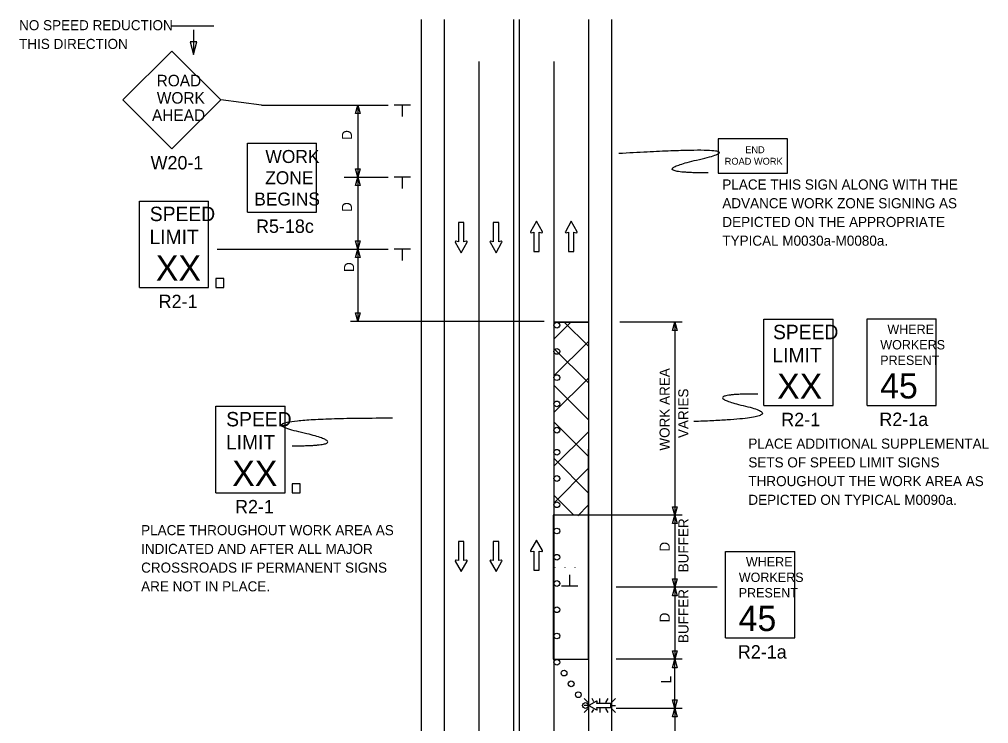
# Model space of a CAD drawing. Extents: x 16747 to 18480, y 5932 to 6921.
# Drawn here: x 16747 to 17419, y 6432 to 6921 of the extents above; entities that cross this region are included whole.
import ezdxf

# ---------------------------------------------------------------- set-up
doc = ezdxf.new("R2010")
doc.units = 0
for name, color, linetype in [('ALI_LEGAL_EX', 7, 'Continuous'), ('MT_SCRATCH_LEVEL_E', 7, 'Continuous'), ('PAVT_EDGE_EX', 7, 'Continuous'), ('TRAFFIC_SIGNS_PR', 7, 'Continuous'), ('TYPICAL_TEXT_DIMEN_PR', 7, 'Continuous')]:
    doc.layers.add(name, color=color, linetype=linetype)

msp = doc.modelspace()

# ---------------------------------------------------------------- linework, layer by layer
at = {"layer": 'ALI_LEGAL_EX'}
for p, q in [((17065.33, 6891.74), (17065.33, 6062.55)), ((17117.33, 6891.74), (17117.33, 6062.55))]:
    msp.add_line(p, q, dxfattribs=at)
for points in [[(17065.33, 6809.08), (17065.33, 6784.08)], [(17117.33, 6809.08), (17117.33, 6784.08)], [(17065.33, 6709.08), (17065.33, 6684.08)], [(17117.33, 6709.08), (17117.33, 6684.08)], [(17065.33, 6609.08), (17065.33, 6584.08)], [(17117.33, 6609.08), (17117.33, 6584.08)], [(17117.33, 6541.14), (17117.33, 6516.14)], [(17065.33, 6509.08), (17065.33, 6484.08)]]:
    msp.add_lwpolyline(points, dxfattribs=at)
at = {"layer": 'MT_SCRATCH_LEVEL_E'}
for p, q in [((17055, 6779.96), (17051.26, 6779.96)), ((17051.26, 6779.96), (17051.26, 6766.71)), ((17055, 6779.96), (17051.26, 6779.96)), ((17051.26, 6779.96), (17051.26, 6766.71)), ((17055, 6766.71), (17055, 6779.96)), ((17055, 6766.71), (17055, 6779.96)), ((17079.07, 6779.96), (17075.33, 6779.96)), ((17075.33, 6779.96), (17075.33, 6766.71)), ((17079.07, 6779.96), (17075.33, 6779.96)), ((17075.33, 6779.96), (17075.33, 6766.71)), ((17079.07, 6766.71), (17079.07, 6779.96)), ((17079.07, 6766.71), (17079.07, 6779.96)), ((17105.26, 6780.91), (17101.15, 6773.67)), ((17105.26, 6780.91), (17101.15, 6773.67)), ((17109.41, 6773.67), (17105.26, 6780.91)), ((17109.41, 6773.67), (17105.26, 6780.91)), ((17129.43, 6780.91), (17125.32, 6773.67)), ((17129.43, 6780.91), (17125.32, 6773.67)), ((17133.58, 6773.67), (17129.43, 6780.91)), ((17133.58, 6773.67), (17129.43, 6780.91)), ((17101.63, 6772.99), (17103.41, 6773.3)), ((17101.63, 6772.99), (17103.41, 6773.3)), ((17103.41, 6773.3), (17103.41, 6760.04)), ((17103.41, 6773.3), (17103.41, 6760.04)), ((17107.15, 6760.04), (17107.15, 6773.3)), ((17107.15, 6773.3), (17108.93, 6772.99)), ((17107.15, 6760.04), (17107.15, 6773.3)), ((17107.15, 6773.3), (17108.93, 6772.99)), ((17125.8, 6772.99), (17127.58, 6773.3)), ((17125.8, 6772.99), (17127.58, 6773.3)), ((17127.58, 6773.3), (17127.58, 6760.04)), ((17127.58, 6773.3), (17127.58, 6760.04)), ((17131.32, 6760.04), (17131.32, 6773.3)), ((17131.32, 6773.3), (17133.1, 6772.99)), ((17131.32, 6760.04), (17131.32, 6773.3)), ((17131.32, 6773.3), (17133.1, 6772.99)), ((17049, 6766.34), (17053.15, 6759.1)), ((17049, 6766.34), (17053.15, 6759.1)), ((17051.26, 6766.71), (17049.48, 6767.02)), ((17051.26, 6766.71), (17049.48, 6767.02)), ((17053.15, 6759.1), (17057.26, 6766.34)), ((17053.15, 6759.1), (17057.26, 6766.34)), ((17056.78, 6767.02), (17055, 6766.71)), ((17056.78, 6767.02), (17055, 6766.71)), ((17073.07, 6766.34), (17077.22, 6759.1)), ((17073.07, 6766.34), (17077.22, 6759.1)), ((17075.33, 6766.71), (17073.55, 6767.02)), ((17075.33, 6766.71), (17073.55, 6767.02)), ((17077.22, 6759.1), (17081.33, 6766.34)), ((17077.22, 6759.1), (17081.33, 6766.34)), ((17080.85, 6767.02), (17079.07, 6766.71)), ((17080.85, 6767.02), (17079.07, 6766.71)), ((17103.41, 6760.04), (17107.15, 6760.04)), ((17103.41, 6760.04), (17107.15, 6760.04)), ((17127.58, 6760.04), (17131.32, 6760.04)), ((17127.58, 6760.04), (17131.32, 6760.04)), ((17055, 6558.64), (17051.26, 6558.64)), ((17051.26, 6558.64), (17051.26, 6545.38)), ((17055, 6558.64), (17051.26, 6558.64)), ((17051.26, 6558.64), (17051.26, 6545.38)), ((17055, 6545.38), (17055, 6558.64)), ((17055, 6545.38), (17055, 6558.64)), ((17079.07, 6558.64), (17075.33, 6558.64)), ((17075.33, 6558.64), (17075.33, 6545.38)), ((17079.07, 6558.64), (17075.33, 6558.64)), ((17075.33, 6558.64), (17075.33, 6545.38)), ((17079.07, 6545.38), (17079.07, 6558.64)), ((17079.07, 6545.38), (17079.07, 6558.64)), ((17105.26, 6559.59), (17101.15, 6552.35)), ((17105.26, 6559.59), (17101.15, 6552.35)), ((17109.41, 6552.35), (17105.26, 6559.59)), ((17109.41, 6552.35), (17105.26, 6559.59)), ((17101.63, 6551.66), (17103.41, 6551.98)), ((17101.63, 6551.66), (17103.41, 6551.98)), ((17103.41, 6551.98), (17103.41, 6538.72)), ((17103.41, 6551.98), (17103.41, 6538.72)), ((17107.15, 6538.72), (17107.15, 6551.98)), ((17107.15, 6551.98), (17108.93, 6551.66)), ((17107.15, 6538.72), (17107.15, 6551.98)), ((17107.15, 6551.98), (17108.93, 6551.66)), ((17049, 6545.01), (17053.15, 6537.77)), ((17049, 6545.01), (17053.15, 6537.77)), ((17051.26, 6545.38), (17049.48, 6545.7)), ((17051.26, 6545.38), (17049.48, 6545.7)), ((17053.15, 6537.77), (17057.26, 6545.01)), ((17053.15, 6537.77), (17057.26, 6545.01)), ((17056.78, 6545.7), (17055, 6545.38)), ((17056.78, 6545.7), (17055, 6545.38)), ((17073.07, 6545.01), (17077.22, 6537.77)), ((17073.07, 6545.01), (17077.22, 6537.77)), ((17075.33, 6545.38), (17073.55, 6545.7)), ((17075.33, 6545.38), (17073.55, 6545.7)), ((17077.22, 6537.77), (17081.33, 6545.01)), ((17077.22, 6537.77), (17081.33, 6545.01)), ((17080.85, 6545.7), (17079.07, 6545.38)), ((17080.85, 6545.7), (17079.07, 6545.38)), ((17103.41, 6538.72), (17107.15, 6538.72)), ((17103.41, 6538.72), (17107.15, 6538.72))]:
    msp.add_line(p, q, dxfattribs=at)
for centre, start, end in [((17101.56, 6773.45), 150.42484, 279.96381), ((17101.56, 6773.45), 150.42484, 279.96381), ((17109, 6773.45), 260.03619, 29.77312), ((17109, 6773.45), 260.03619, 29.77312), ((17125.73, 6773.45), 150.42484, 279.96381), ((17125.73, 6773.45), 150.42484, 279.96381), ((17133.17, 6773.45), 260.03619, 29.77312), ((17133.17, 6773.45), 260.03619, 29.77312), ((17049.41, 6766.56), 80.03619, 209.77312), ((17049.41, 6766.56), 80.03619, 209.77312), ((17056.85, 6766.56), 330.42484, 99.96381), ((17056.85, 6766.56), 330.42484, 99.96381), ((17073.48, 6766.56), 80.03619, 209.77312), ((17073.48, 6766.56), 80.03619, 209.77312), ((17080.92, 6766.56), 330.42484, 99.96381), ((17080.92, 6766.56), 330.42484, 99.96381), ((17101.56, 6552.12), 150.42484, 279.96381), ((17101.56, 6552.12), 150.42484, 279.96381), ((17109, 6552.12), 260.03619, 29.77312), ((17109, 6552.12), 260.03619, 29.77312), ((17049.41, 6545.24), 80.03619, 209.77312), ((17049.41, 6545.24), 80.03619, 209.77312), ((17056.85, 6545.24), 330.42484, 99.96381), ((17056.85, 6545.24), 330.42484, 99.96381), ((17073.48, 6545.24), 80.03619, 209.77312), ((17073.48, 6545.24), 80.03619, 209.77312), ((17080.92, 6545.24), 330.42484, 99.96381), ((17080.92, 6545.24), 330.42484, 99.96381)]:
    msp.add_arc(centre, 0.463, start, end, dxfattribs=at)
at = {"layer": 'PAVT_EDGE_EX'}
for p, q in [((17025.33, 6921.02), (17025.33, 6117.01)), ((17041.33, 6921.02), (17041.33, 6117.01)), ((17089.33, 6921.02), (17089.33, 6117.01)), ((17093.33, 6921.02), (17093.33, 6117.01)), ((17141.33, 6921.02), (17141.33, 6117.01)), ((17157.33, 6921.02), (17157.33, 6117.01)), ((17141.33, 6710.93), (17117.33, 6710.93)), ((17117.33, 6710.93), (17141.33, 6710.93)), ((17117.33, 6699.03), (17129.23, 6710.93)), ((17141.33, 6694.12), (17124.52, 6710.93)), ((17117.33, 6673.58), (17141.33, 6697.58)), ((17141.33, 6668.67), (17117.33, 6692.67)), ((17117.33, 6648.12), (17141.33, 6672.12)), ((17141.33, 6643.21), (17117.33, 6667.21)), ((17141.33, 6617.76), (17117.33, 6641.76)), ((17117.38, 6610.86), (17141.33, 6634.81)), ((17141.33, 6508.99), (17141.33, 6622.71)), ((17141.24, 6592.39), (17117.69, 6615.94)), ((17117.36, 6585.38), (17141.23, 6609.25)), ((17131.12, 6577.05), (17117.72, 6590.46)), ((17134.01, 6576.58), (17141.2, 6583.77)), ((17117.33, 6541.04), (17117.33, 6541.04)), ((17118.26, 6540.69), (17118.31, 6540.8)), ((17125.14, 6540.69), (17125.19, 6540.8)), ((17132.03, 6540.69), (17132.08, 6540.8)), ((17141.33, 6508.99), (17141.33, 6541.04)), ((17117.33, 6476.93), (17141.33, 6476.93)), ((17117.33, 6476.93), (17141.33, 6476.93))]:
    msp.add_line(p, q, dxfattribs=at)
msp.add_lwpolyline([(17141.33, 6576.93), (17116.95, 6576.93), (17116.95, 6476.93), (17141.33, 6476.93)], close=True, dxfattribs=at)
at = {"layer": 'TRAFFIC_SIGNS_PR'}
for p, q in [((16852.37, 6899.07), (16818.43, 6865.13)), ((16886.31, 6865.13), (16852.37, 6899.07)), ((16818.43, 6865.13), (16852.37, 6831.19)), ((16852.37, 6831.19), (16886.31, 6865.13)), ((16904.74, 6787.14), (16904.74, 6835.14)), ((16904.74, 6835.14), (16952.74, 6835.14)), ((16952.74, 6787.14), (16952.74, 6835.14)), ((16829.85, 6794.94), (16877.85, 6794.94)), ((16829.85, 6734.94), (16829.85, 6794.94)), ((16877.85, 6734.94), (16877.85, 6794.94)), ((16904.74, 6787.14), (16952.74, 6787.14)), ((16829.85, 6734.94), (16877.85, 6734.94)), ((17263.11, 6712.99), (17311.11, 6712.99)), ((17263.11, 6652.99), (17263.11, 6712.99)), ((17311.11, 6652.99), (17311.11, 6712.99)), ((17334.6, 6713.1), (17382.6, 6713.1)), ((17334.6, 6653.1), (17334.6, 6713.1)), ((17382.6, 6653.1), (17382.6, 6713.1)), ((16882.84, 6652.48), (16930.84, 6652.48)), ((16882.84, 6592.48), (16882.84, 6652.48)), ((16930.84, 6592.48), (16930.84, 6652.48)), ((17263.11, 6652.99), (17311.11, 6652.99)), ((17334.6, 6653.1), (17382.6, 6653.1)), ((16882.84, 6592.48), (16930.84, 6592.48)), ((17236.44, 6551.71), (17284.44, 6551.71)), ((17236.44, 6491.71), (17236.44, 6551.71)), ((17284.44, 6491.71), (17284.44, 6551.71)), ((17236.44, 6491.71), (17284.44, 6491.71)), ((17138.37, 6449.64), (17141.19, 6446.82)), ((17145.09, 6447.46), (17143.83, 6449.64)), ((17149.28, 6446.82), (17149.28, 6449.64)), ((17153.41, 6446.82), (17155.04, 6449.64)), ((17157.36, 6446.82), (17160.18, 6449.64)), ((17141.19, 6444.79), (17138.37, 6444.79)), ((17138.37, 6439.94), (17141.19, 6442.76)), ((17143.81, 6439.94), (17145.01, 6442.03)), ((17149.28, 6442.76), (17149.28, 6439.94)), ((17155.06, 6439.94), (17153.44, 6442.76)), ((17157.36, 6444.79), (17160.18, 6444.79)), ((17157.36, 6442.76), (17160.18, 6439.94))]:
    msp.add_line(p, q, dxfattribs=at)
for points in [[(17231.37, 6814.23), (17279.37, 6814.23), (17279.37, 6838.23), (17231.37, 6838.23)], [(16882.86, 6734.94), (16888.46, 6734.94), (16888.46, 6741.11), (16882.86, 6741.11)], [(16935.86, 6592.48), (16941.45, 6592.48), (16941.45, 6598.65), (16935.86, 6598.65)]]:
    msp.add_lwpolyline(points, close=True, dxfattribs=at)
for points in [[(17146.95, 6447.81), (17141.64, 6444.79), (17146.95, 6441.75)], [(17147.45, 6442.11), (17147.22, 6443.41), (17156.94, 6443.41), (17156.94, 6446.15), (17147.22, 6446.15), (17147.45, 6447.45)]]:
    msp.add_lwpolyline(points, dxfattribs=at)
for centre in [(17119.43, 6708.81), (17119.43, 6690.6), (17119.43, 6672.38), (17119.43, 6654.17), (17119.43, 6635.96), (17119.43, 6620.59), (17119.43, 6602.37), (17119.43, 6584.16), (17119.43, 6565.95), (17119.43, 6547.73), (17119.43, 6529.52), (17119.43, 6511.3), (17119.43, 6493.09), (17119.43, 6474.87), (17124.4, 6467.36), (17129.37, 6459.86), (17134.33, 6452.36), (17139.3, 6444.85)]:
    msp.add_circle(centre, 2, dxfattribs=at)
for centre, start, end in [((17147.11, 6447.51), 350.73078, 118.89165), ((17147.11, 6442.05), 241.48329, 9.95933)]:
    msp.add_arc(centre, 0.341, start, end, dxfattribs=at)
for points in [[(17224.3, 6814.48), (17177.06, 6814.48), (17262.08, 6833.83), (17162.37, 6827.87)], [(17258.77, 6661.03), (17214.68, 6661.03), (17285.83, 6644.17), (17214.39, 6641.93)], [(16935.75, 6625.08), (16982.98, 6625.08), (16897.96, 6644.42), (17005.44, 6644.42)]]:
    msp.add_open_spline(points, degree=2, dxfattribs=at)
at = {"layer": 'TYPICAL_TEXT_DIMEN_PR'}
for p, q in [((16881.52, 6916.37), (16852.08, 6916.37)), ((16867.34, 6913.87), (16867.34, 6896.75)), ((16867.34, 6905.54), (16864.99, 6905.54)), ((16864.99, 6905.54), (16867.34, 6896.75)), ((16867.34, 6896.75), (16869.7, 6905.54)), ((16869.7, 6905.54), (16867.34, 6905.54)), ((16914.61, 6861.51), (16886.31, 6865.13)), ((16914.61, 6861.51), (17002.33, 6861.51)), ((16979.76, 6855.65), (16981.33, 6861.51)), ((16981.33, 6861.51), (16981.33, 6811.51)), ((16981.33, 6861.51), (16982.9, 6855.65)), ((17017.83, 6861.51), (17006.58, 6861.51)), ((17012.2, 6861.51), (17012.2, 6853.72)), ((16981.33, 6855.65), (16979.76, 6855.65)), ((16982.9, 6855.65), (16981.33, 6855.65)), ((16971.78, 6811.51), (17002.33, 6811.51)), ((16981.33, 6811.51), (16979.76, 6817.37)), ((16979.76, 6817.37), (16981.33, 6817.37)), ((16979.76, 6805.65), (16981.33, 6811.51)), ((16981.33, 6817.37), (16982.9, 6817.37)), ((16982.9, 6817.37), (16981.33, 6811.51)), ((16981.33, 6811.51), (16981.33, 6761.51)), ((16981.33, 6811.51), (16982.9, 6805.65)), ((17017.83, 6811.51), (17006.58, 6811.51)), ((17012.2, 6811.51), (17012.2, 6803.72)), ((16981.33, 6805.65), (16979.76, 6805.65)), ((16982.9, 6805.65), (16981.33, 6805.65)), ((16981.33, 6761.51), (16979.76, 6767.37)), ((16979.76, 6767.37), (16981.33, 6767.37)), ((16981.33, 6767.37), (16982.9, 6767.37)), ((16982.9, 6767.37), (16981.33, 6761.51)), ((16883.79, 6761.51), (17002.33, 6761.51)), ((16979.76, 6755.65), (16981.33, 6761.51)), ((16981.33, 6761.51), (16981.33, 6711.51)), ((16981.33, 6761.51), (16982.9, 6755.65)), ((17017.83, 6761.51), (17006.58, 6761.51)), ((17012.2, 6761.51), (17012.2, 6753.72)), ((16981.33, 6755.65), (16979.76, 6755.65)), ((16982.9, 6755.65), (16981.33, 6755.65)), ((16981.33, 6711.51), (16979.76, 6717.37)), ((16979.76, 6717.37), (16981.33, 6717.37)), ((16981.33, 6717.37), (16982.9, 6717.37)), ((16982.9, 6717.37), (16981.33, 6711.51)), ((16976.33, 6711.51), (17110.71, 6711.51)), ((17206.33, 6710.93), (17163.13, 6710.93)), ((17199.76, 6705.07), (17201.33, 6710.93)), ((17201.33, 6710.93), (17202.9, 6705.07)), ((17201.33, 6710.93), (17201.33, 6576.93)), ((17201.33, 6705.07), (17199.76, 6705.07)), ((17202.9, 6705.07), (17201.33, 6705.07)), ((17201.33, 6576.93), (17199.76, 6582.79)), ((17199.76, 6582.79), (17201.33, 6582.79)), ((17201.33, 6582.79), (17202.9, 6582.79)), ((17202.9, 6582.79), (17201.33, 6576.93)), ((17206.33, 6576.93), (17141.33, 6576.93)), ((17199.76, 6571.06), (17201.33, 6576.93)), ((17201.33, 6576.93), (17201.33, 6526.93)), ((17201.33, 6576.93), (17202.9, 6571.06)), ((17201.33, 6571.06), (17199.76, 6571.06)), ((17202.9, 6571.06), (17201.33, 6571.06)), ((17128.35, 6527.67), (17128.35, 6535.45)), ((17201.33, 6526.93), (17199.76, 6532.79)), ((17199.76, 6532.79), (17201.33, 6532.79)), ((17201.33, 6532.79), (17202.9, 6532.79)), ((17202.9, 6532.79), (17201.33, 6526.93)), ((17133.98, 6527.67), (17122.73, 6527.67)), ((17230.58, 6526.93), (17160.63, 6526.93)), ((17199.76, 6521.06), (17201.33, 6526.93)), ((17201.33, 6526.93), (17202.9, 6521.06)), ((17201.33, 6526.93), (17201.33, 6476.93)), ((17201.33, 6521.06), (17199.76, 6521.06)), ((17202.9, 6521.06), (17201.33, 6521.06)), ((17201.33, 6476.93), (17199.76, 6482.79)), ((17199.76, 6482.79), (17201.33, 6482.79)), ((17201.33, 6482.79), (17202.9, 6482.79)), ((17202.9, 6482.79), (17201.33, 6476.93)), ((17206.33, 6476.93), (17160.63, 6476.93)), ((17199.76, 6471.06), (17201.33, 6476.93)), ((17201.33, 6442.82), (17201.33, 6476.93)), ((17201.33, 6476.93), (17202.9, 6471.06)), ((17201.33, 6471.06), (17199.76, 6471.06)), ((17202.9, 6471.06), (17201.33, 6471.06)), ((17201.33, 6442.82), (17199.76, 6448.68)), ((17199.76, 6448.68), (17201.33, 6448.68)), ((17201.33, 6448.68), (17202.9, 6448.68)), ((17202.9, 6448.68), (17201.33, 6442.82)), ((17206.33, 6442.82), (17160.63, 6442.82)), ((17199.76, 6436.95), (17201.33, 6442.82)), ((17201.33, 6442.82), (17201.33, 6392.82)), ((17201.33, 6442.82), (17202.9, 6436.95)), ((17201.33, 6436.95), (17199.76, 6436.95)), ((17202.9, 6436.95), (17201.33, 6436.95))]:
    msp.add_line(p, q, dxfattribs=at)

# ---------------------------------------------------------------- texts
at = {"layer": 'TRAFFIC_SIGNS_PR'}
for s, height, p in [('ROAD', 8, (16841.79, 6874.55)), ('WORK', 8, (16841.93, 6862.55)), ('AHEAD', 8, (16838.57, 6850.55)), ('END', 4.789, (17250.12, 6828.14)), ('W20-1', 9.3, (16837.58, 6816.89)), ('WORK', 9.021, (16917.24, 6821.35)), ('ROAD WORK', 4.789, (17235.88, 6820.16)), ('ZONE', 9.021, (16917.09, 6806.59)), ('PLACE THIS SIGN ALONG WITH THE', 7, (17234.25, 6802.94)), ('BEGINS', 9.021, (16909.5, 6791.83)), ('ADVANCE WORK ZONE SIGNING AS', 7, (17234.25, 6789.94)), ('SPEED', 10, (16837.05, 6781.02)), ('R5-18c', 9.3, (16910.75, 6772.84)), ('DEPICTED ON THE APPROPRIATE', 7, (17234.25, 6776.94)), ('LIMIT', 10, (16836.85, 6765.02)), ('TYPICAL M0030a-M0080a.', 7, (17234.25, 6763.94)), ('XX', 17.538, (16841.24, 6739.64)), ('R2-1', 9.3, (16843.19, 6720.64)), ('SPEED', 10, (17269.4, 6699.07)), ('WHERE', 6.5, (17348.74, 6702.71)), ('WORKERS', 6.5, (17343.83, 6691.96)), ('LIMIT', 10, (17268.98, 6683.07)), ('PRESENT', 6.5, (17343.74, 6681.21)), ('XX', 17.538, (17272.24, 6657.69)), ('45', 17.538, (17343.73, 6657.92)), ('SPEED', 10, (16890.05, 6638.56)), ('R2-1', 9.3, (17275.12, 6638.69)), ('R2-1a', 9.3, (17343.17, 6638.8)), ('LIMIT', 10, (16889.85, 6622.56)), ('PLACE ADDITIONAL SUPPLEMENTAL', 7, (17252.3, 6623.09)), ('SETS OF SPEED LIMIT SIGNS', 7, (17252.3, 6610.09)), ('XX', 17.538, (16894.23, 6597.18)), ('THROUGHOUT THE WORK AREA AS', 7, (17252.3, 6597.09)), ('DEPICTED ON TYPICAL M0090a.', 7, (17252.3, 6584.09)), ('R2-1', 9.3, (16896.19, 6578.18)), ('PLACE THROUGHOUT WORK AREA AS', 7, (16831.03, 6563.04)), ('INDICATED AND AFTER ALL MAJOR', 7, (16831.03, 6550.04)), ('CROSSROADS IF PERMANENT SIGNS', 7, (16831.03, 6537.04)), ('WHERE', 6.5, (17250.58, 6541.32)), ('WORKERS', 6.5, (17245.67, 6530.57)), ('ARE NOT IN PLACE.', 7, (16831.03, 6524.04)), ('PRESENT', 6.5, (17245.59, 6519.82)), ('45', 17.538, (17245.58, 6496.53)), ('R2-1a', 9.3, (17245.01, 6477.41))]:
    msp.add_text(s, height=height, dxfattribs=at).set_placement(p)
at = {"layer": 'TYPICAL_TEXT_DIMEN_PR'}
for s, p in [('NO SPEED REDUCTION', (16746.36, 6913.49)), ('THIS DIRECTION', (16746.36, 6900.49))]:
    msp.add_text(s, height=7, dxfattribs=at).set_placement(p)
for s, p in [('D', (16977.28, 6837.39)), ('D', (16977.28, 6787.39)), ('D', (16978.77, 6745.73)), ('WORK AREA', (17197.67, 6621.73)), ('VARIES', (17210.67, 6630.45)), ('BUFFER', (17210.75, 6537.3)), ('D', (17197.75, 6551.66)), ('BUFFER', (17210.75, 6488.21)), ('D', (17197.75, 6502.57)), ('L', (17198.77, 6460.22))]:
    msp.add_text(s, height=7, rotation=90, dxfattribs=at).set_placement(p)

doc.saveas('drawing.dxf')
